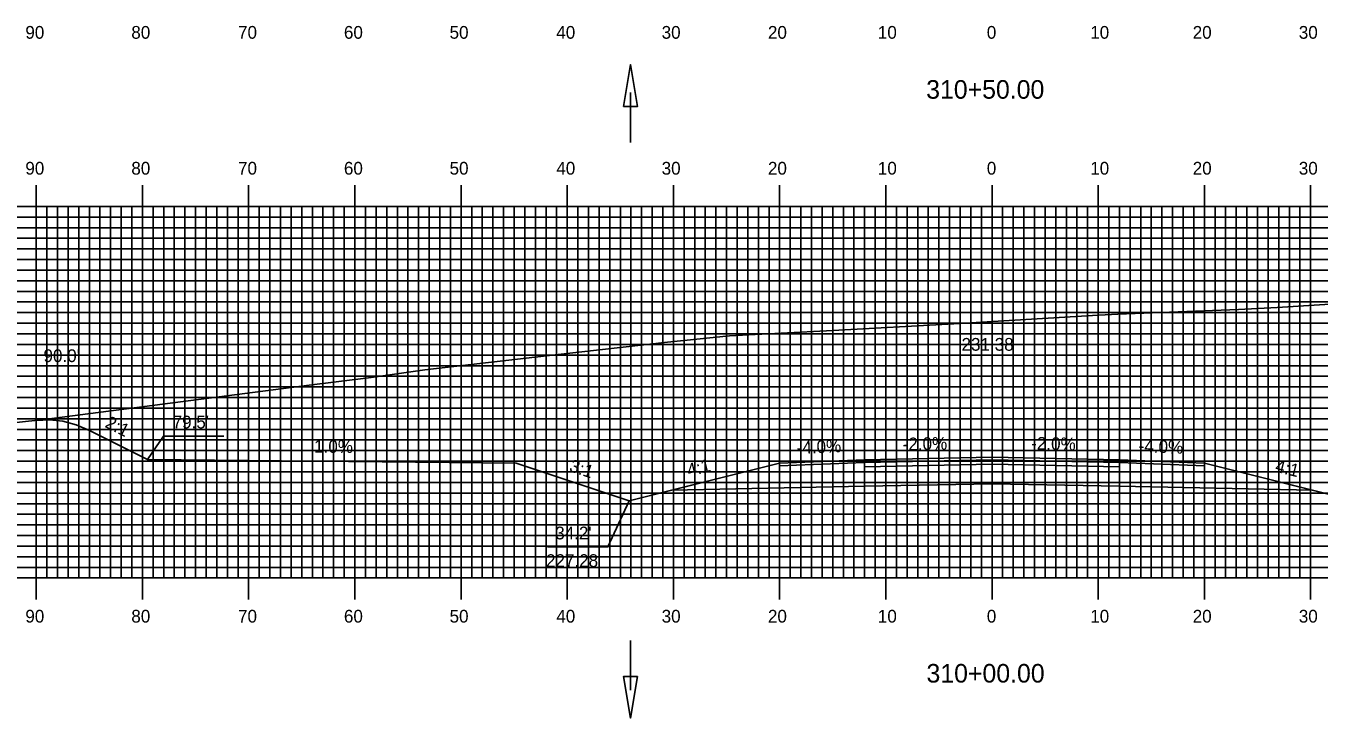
# Model space of a CAD drawing. Extents: x 1818063 to 1818407, y 442591 to 442811.
# Drawn here: x 1818138.1 to 1818259.9, y 442650.5 to 442715.7 of the extents above; entities that cross this region are included whole.
import ezdxf

# ---------------------------------------------------------------- set-up
doc = ezdxf.new("R2010")
doc.units = 0
for name, color, linetype in [('ANNOTATION', 7, 'Continuous'), ('D_Drainage_Ditch_Line', 7, 'Continuous'), ('D_Roadway_Centerline', 7, 'Continuous'), ('D_Roadway_Centerline_Text', 7, 'Continuous'), ('D_Roadway_Edge_Shoulder', 7, 'Continuous'), ('D_Roadway_Edge_TW', 7, 'Continuous'), ('D_Roadway_Pavement', 7, 'Continuous'), ('D_Roadway_SlopeLines', 7, 'Continuous'), ('D_Roadway_SubGrade', 7, 'Continuous'), ('D_Text_Standard', 7, 'Continuous'), ('H_V ANNOTATION', 7, 'Continuous'), ('MAJOR', 7, 'Continuous'), ('MINOR', 7, 'Continuous'), ('S_Roadway_Centerline', 7, 'Continuous')]:
    doc.layers.add(name, color=color, linetype=linetype)

msp = doc.modelspace()

# ---------------------------------------------------------------- linework, layer by layer
at = {"layer": 'ANNOTATION'}
for points in [[(1818156.8, 442677.03), (1818151.1, 442677.03), (1818149.59, 442674.83)], [(1818187.27, 442666.59), (1818192.96, 442666.59), (1818194.95, 442670.94)]]:
    msp.add_lwpolyline(points, dxfattribs=at)
at = {"layer": 'D_Drainage_Ditch_Line'}
for p, q in [((1818195.09, 442709.41), (1818195.09, 442704.71)), ((1818195.09, 442653.09), (1818195.09, 442657.79))]:
    msp.add_line(p, q, dxfattribs=at)
for points in [[(1818194.43, 442708.09), (1818195.75, 442708.09), (1818195.09, 442712.03)], [(1818195.75, 442654.4), (1818194.43, 442654.4), (1818195.09, 442650.47)]]:
    msp.add_lwpolyline(points, close=True, dxfattribs=at)
at = {"layer": 'D_Roadway_Centerline'}
msp.add_lwpolyline([(1818139.13, 442678.51), (1818140.38, 442678.57), (1818141.63, 442678.43), (1818142.88, 442678.09), (1818144.13, 442677.57), (1818149.59, 442674.83), (1818184.32, 442674.49), (1818194.95, 442670.94), (1818198.95, 442671.94), (1818209.13, 442674.49), (1818217.13, 442674.81), (1818229.13, 442675.05), (1818241.13, 442674.81), (1818249.13, 442674.49), (1818259.3, 442671.94), (1818263.3, 442670.94), (1818273.93, 442674.49), (1818282.26, 442674.57), (1818314.13, 442690.5), (1818315.38, 442691.06), (1818316.63, 442691.48), (1818317.88, 442691.76), (1818319.13, 442691.9)], dxfattribs=at)
at = {"layer": 'D_Roadway_Edge_Shoulder'}
for points in [[(1818217.13, 442674.81), (1818209.13, 442674.49), (1818209.13, 442674.24), (1818217.13, 442674.56)], [(1818241.13, 442674.81), (1818249.13, 442674.49), (1818249.13, 442674.24), (1818241.13, 442674.56)]]:
    msp.add_lwpolyline(points, close=True, dxfattribs=at)
at = {"layer": 'D_Roadway_Edge_TW'}
msp.add_lwpolyline([(1818217.13, 442674.56), (1818217.13, 442674.81), (1818229.13, 442675.05), (1818241.13, 442674.81), (1818241.13, 442674.56), (1818229.13, 442674.8)], close=True, dxfattribs=at)
at = {"layer": 'D_Roadway_Pavement'}
msp.add_lwpolyline([(1818217.13, 442674.14), (1818217.13, 442674.56), (1818229.13, 442674.8), (1818241.13, 442674.56), (1818241.13, 442674.14), (1818229.13, 442674.38)], close=True, dxfattribs=at)
at = {"layer": 'D_Roadway_SlopeLines'}
for points in [[(1818184.32, 442674.49), (1818149.59, 442674.83), (1818144.13, 442677.57), (1818142.88, 442678.09), (1818141.63, 442678.43), (1818140.38, 442678.57), (1818139.13, 442678.51)], [(1818194.95, 442670.94), (1818184.32, 442674.49)], [(1818209.13, 442674.49), (1818194.95, 442670.94)], [(1818249.13, 442674.49), (1818263.3, 442670.94)]]:
    msp.add_lwpolyline(points, dxfattribs=at)
at = {"layer": 'D_Roadway_SubGrade'}
msp.add_lwpolyline([(1818217.13, 442672.31), (1818198.95, 442671.94), (1818209.13, 442674.49), (1818209.13, 442674.24), (1818217.13, 442674.56), (1818229.13, 442674.8), (1818241.13, 442674.56), (1818249.13, 442674.24), (1818249.13, 442674.49), (1818259.3, 442671.94), (1818241.13, 442672.31), (1818229.13, 442672.55)], close=True, dxfattribs=at)
at = {"layer": 'MAJOR'}
for p, q in [((1818139.13, 442700.67), (1818139.13, 442698.67)), ((1818149.13, 442700.67), (1818149.13, 442698.67)), ((1818159.13, 442700.67), (1818159.13, 442698.67)), ((1818169.13, 442700.67), (1818169.13, 442698.67)), ((1818179.13, 442700.67), (1818179.13, 442698.67)), ((1818189.13, 442700.67), (1818189.13, 442698.67)), ((1818199.13, 442700.67), (1818199.13, 442698.67)), ((1818209.13, 442700.67), (1818209.13, 442698.67)), ((1818219.13, 442700.67), (1818219.13, 442698.67)), ((1818229.13, 442700.67), (1818229.13, 442698.67)), ((1818239.13, 442700.67), (1818239.13, 442698.67)), ((1818249.13, 442700.67), (1818249.13, 442698.67)), ((1818259.13, 442700.67), (1818259.13, 442698.67)), ((1818089.13, 442698.67), (1818369.13, 442698.67)), ((1818089.13, 442698.67), (1818369.13, 442698.67)), ((1818139.13, 442663.67), (1818139.13, 442698.67)), ((1818149.13, 442663.67), (1818149.13, 442698.67)), ((1818159.13, 442663.67), (1818159.13, 442698.67)), ((1818169.13, 442663.67), (1818169.13, 442698.67)), ((1818179.13, 442663.67), (1818179.13, 442698.67)), ((1818189.13, 442663.67), (1818189.13, 442698.67)), ((1818199.13, 442663.67), (1818199.13, 442698.67)), ((1818209.13, 442663.67), (1818209.13, 442698.67)), ((1818219.13, 442663.67), (1818219.13, 442698.67)), ((1818229.13, 442663.67), (1818229.13, 442698.67)), ((1818239.13, 442663.67), (1818239.13, 442698.67)), ((1818249.13, 442663.67), (1818249.13, 442698.67)), ((1818259.13, 442663.67), (1818259.13, 442698.67)), ((1818089.13, 442693.67), (1818369.13, 442693.67)), ((1818089.13, 442688.67), (1818369.13, 442688.67)), ((1818089.13, 442683.67), (1818369.13, 442683.67)), ((1818089.13, 442678.67), (1818369.13, 442678.67)), ((1818089.13, 442673.67), (1818369.13, 442673.67)), ((1818089.13, 442668.67), (1818369.13, 442668.67)), ((1818089.13, 442663.67), (1818369.13, 442663.67)), ((1818089.13, 442663.67), (1818369.13, 442663.67)), ((1818139.13, 442661.66), (1818139.13, 442663.67)), ((1818149.13, 442661.66), (1818149.13, 442663.67)), ((1818159.13, 442661.66), (1818159.13, 442663.67)), ((1818169.13, 442661.66), (1818169.13, 442663.67)), ((1818179.13, 442661.66), (1818179.13, 442663.67)), ((1818189.13, 442661.66), (1818189.13, 442663.67)), ((1818199.13, 442661.66), (1818199.13, 442663.67)), ((1818209.13, 442661.66), (1818209.13, 442663.67)), ((1818219.13, 442661.66), (1818219.13, 442663.67)), ((1818229.13, 442661.66), (1818229.13, 442663.67)), ((1818239.13, 442661.66), (1818239.13, 442663.67)), ((1818249.13, 442661.66), (1818249.13, 442663.67)), ((1818259.13, 442661.66), (1818259.13, 442663.67))]:
    msp.add_line(p, q, dxfattribs=at)
at = {"layer": 'MINOR'}
for p, q in [((1818140.13, 442663.67), (1818140.13, 442698.67)), ((1818141.13, 442663.67), (1818141.13, 442698.67)), ((1818142.13, 442663.67), (1818142.13, 442698.67)), ((1818143.13, 442663.67), (1818143.13, 442698.67)), ((1818144.13, 442663.67), (1818144.13, 442698.67)), ((1818145.13, 442663.67), (1818145.13, 442698.67)), ((1818146.13, 442663.67), (1818146.13, 442698.67)), ((1818147.13, 442663.67), (1818147.13, 442698.67)), ((1818148.13, 442663.67), (1818148.13, 442698.67)), ((1818150.13, 442663.67), (1818150.13, 442698.67)), ((1818151.13, 442663.67), (1818151.13, 442698.67)), ((1818152.13, 442663.67), (1818152.13, 442698.67)), ((1818153.13, 442663.67), (1818153.13, 442698.67)), ((1818154.13, 442663.67), (1818154.13, 442698.67)), ((1818155.13, 442663.67), (1818155.13, 442698.67)), ((1818156.13, 442663.67), (1818156.13, 442698.67)), ((1818157.13, 442663.67), (1818157.13, 442698.67)), ((1818158.13, 442663.67), (1818158.13, 442698.67)), ((1818160.13, 442663.67), (1818160.13, 442698.67)), ((1818161.13, 442663.67), (1818161.13, 442698.67)), ((1818162.13, 442663.67), (1818162.13, 442698.67)), ((1818163.13, 442663.67), (1818163.13, 442698.67)), ((1818164.13, 442663.67), (1818164.13, 442698.67)), ((1818165.13, 442663.67), (1818165.13, 442698.67)), ((1818166.13, 442663.67), (1818166.13, 442698.67)), ((1818167.13, 442663.67), (1818167.13, 442698.67)), ((1818168.13, 442663.67), (1818168.13, 442698.67)), ((1818170.13, 442663.67), (1818170.13, 442698.67)), ((1818171.13, 442663.67), (1818171.13, 442698.67)), ((1818172.13, 442663.67), (1818172.13, 442698.67)), ((1818173.13, 442663.67), (1818173.13, 442698.67)), ((1818174.13, 442663.67), (1818174.13, 442698.67)), ((1818175.13, 442663.67), (1818175.13, 442698.67)), ((1818176.13, 442663.67), (1818176.13, 442698.67)), ((1818177.13, 442663.67), (1818177.13, 442698.67)), ((1818178.13, 442663.67), (1818178.13, 442698.67)), ((1818180.13, 442663.67), (1818180.13, 442698.67)), ((1818181.13, 442663.67), (1818181.13, 442698.67)), ((1818182.13, 442663.67), (1818182.13, 442698.67)), ((1818183.13, 442663.67), (1818183.13, 442698.67)), ((1818184.13, 442663.67), (1818184.13, 442698.67)), ((1818185.13, 442663.67), (1818185.13, 442698.67)), ((1818186.13, 442663.67), (1818186.13, 442698.67)), ((1818187.13, 442663.67), (1818187.13, 442698.67)), ((1818188.13, 442663.67), (1818188.13, 442698.67)), ((1818190.13, 442663.67), (1818190.13, 442698.67)), ((1818191.13, 442663.67), (1818191.13, 442698.67)), ((1818192.13, 442663.67), (1818192.13, 442698.67)), ((1818193.13, 442663.67), (1818193.13, 442698.67)), ((1818194.13, 442663.67), (1818194.13, 442698.67)), ((1818195.13, 442663.67), (1818195.13, 442698.67)), ((1818196.13, 442663.67), (1818196.13, 442698.67)), ((1818197.13, 442663.67), (1818197.13, 442698.67)), ((1818198.13, 442663.67), (1818198.13, 442698.67)), ((1818200.13, 442663.67), (1818200.13, 442698.67)), ((1818201.13, 442663.67), (1818201.13, 442698.67)), ((1818202.13, 442663.67), (1818202.13, 442698.67)), ((1818203.13, 442663.67), (1818203.13, 442698.67)), ((1818204.13, 442663.67), (1818204.13, 442698.67)), ((1818205.13, 442663.67), (1818205.13, 442698.67)), ((1818206.13, 442663.67), (1818206.13, 442698.67)), ((1818207.13, 442663.67), (1818207.13, 442698.67)), ((1818208.13, 442663.67), (1818208.13, 442698.67)), ((1818210.13, 442663.67), (1818210.13, 442698.67)), ((1818211.13, 442663.67), (1818211.13, 442698.67)), ((1818212.13, 442663.67), (1818212.13, 442698.67)), ((1818213.13, 442663.67), (1818213.13, 442698.67)), ((1818214.13, 442663.67), (1818214.13, 442698.67)), ((1818215.13, 442663.67), (1818215.13, 442698.67)), ((1818216.13, 442663.67), (1818216.13, 442698.67)), ((1818217.13, 442663.67), (1818217.13, 442698.67)), ((1818218.13, 442663.67), (1818218.13, 442698.67)), ((1818220.13, 442663.67), (1818220.13, 442698.67)), ((1818221.13, 442663.67), (1818221.13, 442698.67)), ((1818222.13, 442663.67), (1818222.13, 442698.67)), ((1818223.13, 442663.67), (1818223.13, 442698.67)), ((1818224.13, 442663.67), (1818224.13, 442698.67)), ((1818225.13, 442663.67), (1818225.13, 442698.67)), ((1818226.13, 442663.67), (1818226.13, 442698.67)), ((1818227.13, 442663.67), (1818227.13, 442698.67)), ((1818228.13, 442663.67), (1818228.13, 442698.67)), ((1818230.13, 442663.67), (1818230.13, 442698.67)), ((1818231.13, 442663.67), (1818231.13, 442698.67)), ((1818232.13, 442663.67), (1818232.13, 442698.67)), ((1818233.13, 442663.67), (1818233.13, 442698.67)), ((1818234.13, 442663.67), (1818234.13, 442698.67)), ((1818235.13, 442663.67), (1818235.13, 442698.67)), ((1818236.13, 442663.67), (1818236.13, 442698.67)), ((1818237.13, 442663.67), (1818237.13, 442698.67)), ((1818238.13, 442663.67), (1818238.13, 442698.67)), ((1818240.13, 442663.67), (1818240.13, 442698.67)), ((1818241.13, 442663.67), (1818241.13, 442698.67)), ((1818242.13, 442663.67), (1818242.13, 442698.67)), ((1818243.13, 442663.67), (1818243.13, 442698.67)), ((1818244.13, 442663.67), (1818244.13, 442698.67)), ((1818245.13, 442663.67), (1818245.13, 442698.67)), ((1818246.13, 442663.67), (1818246.13, 442698.67)), ((1818247.13, 442663.67), (1818247.13, 442698.67)), ((1818248.13, 442663.67), (1818248.13, 442698.67)), ((1818250.13, 442663.67), (1818250.13, 442698.67)), ((1818251.13, 442663.67), (1818251.13, 442698.67)), ((1818252.13, 442663.67), (1818252.13, 442698.67)), ((1818253.13, 442663.67), (1818253.13, 442698.67)), ((1818254.13, 442663.67), (1818254.13, 442698.67)), ((1818255.13, 442663.67), (1818255.13, 442698.67)), ((1818256.13, 442663.67), (1818256.13, 442698.67)), ((1818257.13, 442663.67), (1818257.13, 442698.67)), ((1818258.13, 442663.67), (1818258.13, 442698.67)), ((1818089.13, 442697.67), (1818369.13, 442697.67)), ((1818089.13, 442696.67), (1818369.13, 442696.67)), ((1818089.13, 442695.67), (1818369.13, 442695.67)), ((1818089.13, 442694.67), (1818369.13, 442694.67)), ((1818089.13, 442692.67), (1818369.13, 442692.67)), ((1818089.13, 442691.67), (1818369.13, 442691.67)), ((1818089.13, 442690.67), (1818369.13, 442690.67)), ((1818089.13, 442689.67), (1818369.13, 442689.67)), ((1818089.13, 442687.67), (1818369.13, 442687.67)), ((1818089.13, 442686.67), (1818369.13, 442686.67)), ((1818089.13, 442685.67), (1818369.13, 442685.67)), ((1818089.13, 442684.67), (1818369.13, 442684.67)), ((1818089.13, 442682.67), (1818369.13, 442682.67)), ((1818089.13, 442681.67), (1818369.13, 442681.67)), ((1818089.13, 442680.67), (1818369.13, 442680.67)), ((1818089.13, 442679.67), (1818369.13, 442679.67)), ((1818089.13, 442677.67), (1818369.13, 442677.67)), ((1818089.13, 442676.67), (1818369.13, 442676.67)), ((1818089.13, 442675.67), (1818369.13, 442675.67)), ((1818089.13, 442674.67), (1818369.13, 442674.67)), ((1818089.13, 442672.67), (1818369.13, 442672.67)), ((1818089.13, 442671.67), (1818369.13, 442671.67)), ((1818089.13, 442670.67), (1818369.13, 442670.67)), ((1818089.13, 442669.67), (1818369.13, 442669.67)), ((1818089.13, 442667.67), (1818369.13, 442667.67)), ((1818089.13, 442666.67), (1818369.13, 442666.67)), ((1818089.13, 442665.67), (1818369.13, 442665.67)), ((1818089.13, 442664.67), (1818369.13, 442664.67))]:
    msp.add_line(p, q, dxfattribs=at)
at = {"layer": 'S_Roadway_Centerline'}
msp.add_lwpolyline([(1818089.13, 442670.86), (1818100.91, 442672.8), (1818105.29, 442673.54), (1818112.85, 442675.02), (1818118.64, 442676.23), (1818120.53, 442676.51), (1818133.11, 442677.89), (1818139.88, 442678.59), (1818164.83, 442681.85), (1818170.67, 442682.57), (1818171.78, 442682.7), (1818175.73, 442683.27), (1818187.98, 442684.69), (1818198.58, 442685.89), (1818204.4, 442686.48), (1818214.15, 442686.97), (1818225.54, 442687.62), (1818238.58, 442688.41), (1818240.99, 442688.51), (1818252.33, 442688.95), (1818255.97, 442689.14), (1818265.92, 442689.77)], dxfattribs=at)

# ---------------------------------------------------------------- texts
at = {"layer": 'ANNOTATION'}
for s, rotation, p in [('2:1', 333.4349, (1818145.52, 442677.92)), ('1.0%', 359.4271, (1818165.29, 442675.48)), ('-4.0%', 2.2906, (1818210.76, 442675.35)), ('-2.0%', 1.1458, (1818220.73, 442675.68)), ('-2.0%', 358.8542, (1818232.81, 442675.77)), ('-4.0%', 357.7094, (1818242.92, 442675.54)), ('3:1', 341.5652, (1818189.24, 442673.75)), ('4:1', 14.0362, (1818200.57, 442673.21)), ('4:1', 345.9638, (1818255.72, 442673.7))]:
    msp.add_text(s, height=1.2, rotation=rotation, dxfattribs=at).set_placement(p)
for s, p in [("79.5'", (1818151.97, 442677.76)), ("34.2'", (1818188, 442667.31)), ('227.28', (1818187.13, 442664.71))]:
    msp.add_text(s, height=1.2, dxfattribs=at).set_placement(p)
at = {"layer": 'D_Roadway_Centerline'}
for s, p in [('C', (1818229.12, 442675.05)), ('L', (1818229.13, 442675.04))]:
    msp.add_text(s, height=0.0146, dxfattribs=at).set_placement(p)
at = {"layer": 'D_Roadway_Centerline_Text'}
msp.add_text('231.38', height=1.2, dxfattribs=at).set_placement((1818226.26, 442685.08))
at = {"layer": 'D_Text_Standard'}
msp.add_text("90.0'", height=1.2, dxfattribs=at).set_placement((1818139.81, 442684.01))
at = {"layer": 'H_V ANNOTATION'}
for s, height, p in [('90', 1.2, (1818138.1, 442714.47)), ('80', 1.2, (1818148.08, 442714.47)), ('70', 1.2, (1818158.13, 442714.47)), ('60', 1.2, (1818168.1, 442714.47)), ('50', 1.2, (1818178.05, 442714.47)), ('40', 1.2, (1818188.1, 442714.47)), ('30', 1.2, (1818198.02, 442714.47)), ('20', 1.2, (1818208.03, 442714.47)), ('10', 1.2, (1818218.38, 442714.47)), ('0', 1.2, (1818228.64, 442714.47)), ('10', 1.2, (1818238.38, 442714.47)), ('20', 1.2, (1818248.03, 442714.47)), ('30', 1.2, (1818258.02, 442714.47)), ('310+50.00', 1.75, (1818222.93, 442708.82)), ('90', 1.2, (1818138.1, 442701.67)), ('80', 1.2, (1818148.08, 442701.67)), ('70', 1.2, (1818158.13, 442701.67)), ('60', 1.2, (1818168.1, 442701.67)), ('50', 1.2, (1818178.05, 442701.67)), ('40', 1.2, (1818188.1, 442701.67)), ('30', 1.2, (1818198.02, 442701.67)), ('20', 1.2, (1818208.03, 442701.67)), ('10', 1.2, (1818218.38, 442701.67)), ('0', 1.2, (1818228.64, 442701.67)), ('10', 1.2, (1818238.38, 442701.67)), ('20', 1.2, (1818248.03, 442701.67)), ('30', 1.2, (1818258.02, 442701.67)), ('90', 1.2, (1818138.1, 442659.47)), ('80', 1.2, (1818148.08, 442659.47)), ('70', 1.2, (1818158.13, 442659.47)), ('60', 1.2, (1818168.1, 442659.47)), ('50', 1.2, (1818178.05, 442659.47)), ('40', 1.2, (1818188.1, 442659.47)), ('30', 1.2, (1818198.02, 442659.47)), ('20', 1.2, (1818208.03, 442659.47)), ('10', 1.2, (1818218.38, 442659.47)), ('0', 1.2, (1818228.64, 442659.47)), ('10', 1.2, (1818238.38, 442659.47)), ('20', 1.2, (1818248.03, 442659.47)), ('30', 1.2, (1818258.02, 442659.47)), ('310+00.00', 1.75, (1818222.96, 442653.82))]:
    msp.add_text(s, height=height, dxfattribs=at).set_placement(p)

doc.saveas('drawing.dxf')
